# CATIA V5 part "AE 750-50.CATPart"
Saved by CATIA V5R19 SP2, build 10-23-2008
Part number: AE 750-50
Bounding box of the stored display mesh (mm): x -24.865 to 24.865, y -24.997 to 24.997, z 0 to 150
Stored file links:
  C:\Users\Bora\Desktop\3D Katı model\AE serisi\AE 750\AE 750-50.CATPart
  C:\Program Files\Dassault Systemes\B19\intel_a\reffiles\standard\MetricThickPitch.txt
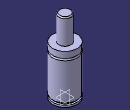
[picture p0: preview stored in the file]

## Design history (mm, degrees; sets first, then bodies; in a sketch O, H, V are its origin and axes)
Body1 (main body)
  Sketch1 on yz-plane, origin (0, 0, 0), H (0, 1, 0), V (0, 0, 1)
    point P1 (25, 82.5)
    point P8 (25, 86.5)
    point P9 (12.5, 148)
    point P11 (12.5, 148)
    point P13 (25, 86.5)
    point P14 (25, 82.5)
    line L1 (25, 82.5) -> (25, 8)
    line L2 (25, 4) -> (25, 0)
    line L3 (21.5, 8) -> (21.5, 4)
    line L4 (25, 99) -> (25, 86.5)
    line L5 (12.5, 148) -> (12.5, 99)
    arc A1 centre (10.5, 148) radius 2 from (12.5, 148) to (10.5, 150) ccw
    arc A2 centre (25, 84.5) radius 2 from (25, 86.5) to (25, 82.5) ccw
    line L6 (10.5, 150) -> (0, 150)
    point P15 (0, 150)
    line L7 (12.5, 99) -> (25, 99)
    line L8 (0, 0) -> (25, 0)
    line L9 (21.5, 8) -> (25, 8)
    line L10 (21.5, 4) -> (25, 4)
    coincidence: P15 V, P1 P14, P8 P13, P9 P11
    tangency: L6 A1
    horizontal: L7 H, L8 H, L9 H, L10 H
  Shaft1: profile Sketch1, axis Sketch1.V, angle 360
  Sketch2 on face of Shaft1 from Sketch1.L8, origin (0, 0, 0), H (1, 0, 0), V (0, -1, 0)
    point P1 (10, 0)
    distance P1 V = 10
  Hole1: placed by Sketch2, at (10, 0, 0) direction (0, 0, 1), diameter 6.647, depth 13, threaded "M8", thread diameter 8, thread depth 13, pitch 1.25
  CircPattern1: of Hole1, instances 2, angular step 180, axis from xy-plane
